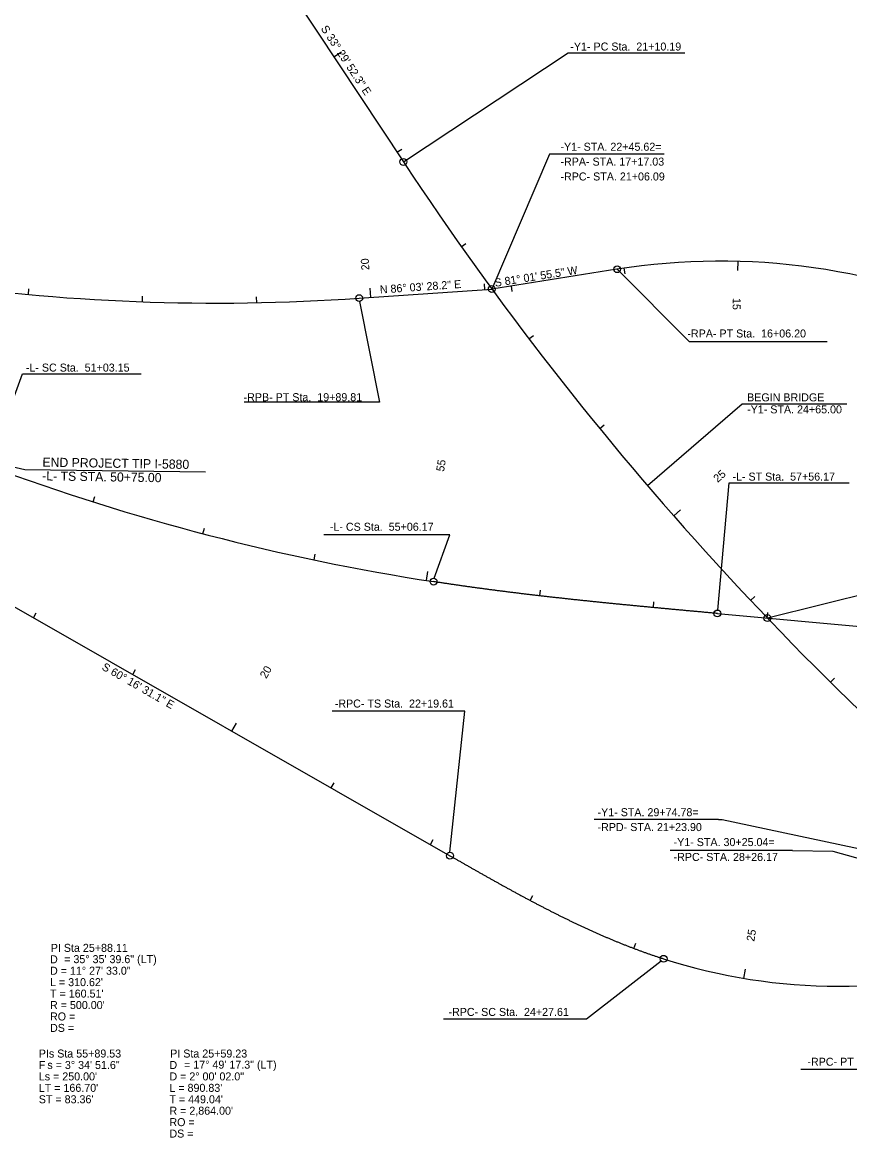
# Model space of a CAD drawing. Extents: x 1636713 to 1642783, y 841520 to 844371.
# Drawn here: x 1640618 to 1641342, y 841942 to 842918 of the extents above; entities that cross this region are included whole.
import ezdxf

# ---------------------------------------------------------------- set-up
doc = ezdxf.new("R2010")
doc.units = 0
for name, color, linetype in [('COGO Default Chain', 7, 'Continuous'), ('Prop DSN White Annotation Label', 7, 'Continuous'), ('Prop Horizontal Alignment', 7, 'Continuous'), ('Prop Horizontal Alignment Curve and Spiral Data', 7, 'Continuous'), ('Prop Horizontal Alignment Direction Label', 7, 'Continuous'), ('Prop Horizontal Alignment Station Label', 7, 'Continuous'), ('Prop Horizontal Alignment Tick Label', 7, 'Continuous'), ('Prop Horizontal Alignment Tick Large', 7, 'Continuous'), ('Prop Horizontal Alignment Tick Small', 7, 'Continuous')]:
    doc.layers.add(name, color=color, linetype=linetype)

msp = doc.modelspace()

# ---------------------------------------------------------------- linework, layer by layer
at = {"layer": 'COGO Default Chain'}
msp.add_line((1640839.83, 842964.49), (1640951.46, 842795.82), dxfattribs=at)
msp.add_arc((1643339.77, 844376.48), 2864, 213.49785, 231.31933, dxfattribs=at)
at = {"layer": 'Prop Horizontal Alignment'}
for p, q in [((1640839.83, 842964.49), (1640951.46, 842795.82)), ((1641138.33, 842701.97), (1641028.85, 842684.69)), ((1640912.85, 842676.7), (1641028.85, 842684.69)), ((1640410.49, 842521.24), (1640992.21, 842189.1)), ((1640410.49, 842521.24), (1640992.21, 842189.1)), ((1641226.26, 842400.92), (1642664.13, 842269.93))]:
    msp.add_line(p, q, dxfattribs=at)
for centre, radius, start, end in [((1643339.77, 844376.48), 2864, 213.49785, 231.31933), ((1640787.73, 844492.39), 1820, 249.39267, 273.94216), ((1641228.74, 842129.06), 580, 64.83812, 98.96792), ((1641283.36, 844405.31), 2000, 249.66813, 261.21372), ((1641332.1, 842574.94), 500, 252.19283, 287.78716), ((1641332.1, 842574.94), 500, 252.19283, 287.78716)]:
    msp.add_arc(centre, radius, start, end, dxfattribs=at)
for points in [[(1641226.26, 842400.92), (1641222.89, 842401.23), (1641219.53, 842401.53), (1641216.16, 842401.84), (1641212.8, 842402.15), (1641209.43, 842402.45), (1641206.07, 842402.76), (1641202.71, 842403.07), (1641199.34, 842403.38), (1641195.98, 842403.69), (1641192.61, 842404), (1641189.25, 842404.31), (1641185.89, 842404.62), (1641182.52, 842404.93), (1641179.16, 842405.25), (1641175.79, 842405.56), (1641172.43, 842405.88), (1641169.07, 842406.19), (1641165.7, 842406.51), (1641162.34, 842406.83), (1641158.98, 842407.15), (1641155.61, 842407.47), (1641152.25, 842407.8), (1641148.89, 842408.13), (1641145.53, 842408.45), (1641142.16, 842408.78), (1641138.8, 842409.11), (1641135.44, 842409.45), (1641132.08, 842409.78), (1641128.72, 842410.12), (1641125.36, 842410.46), (1641121.99, 842410.8), (1641118.63, 842411.15), (1641115.27, 842411.49), (1641111.91, 842411.84), (1641108.55, 842412.2), (1641105.19, 842412.55), (1641101.83, 842412.91), (1641098.48, 842413.27), (1641095.12, 842413.63), (1641091.76, 842414), (1641088.4, 842414.37), (1641085.04, 842414.74), (1641081.68, 842415.12), (1641078.33, 842415.5), (1641074.97, 842415.88), (1641071.61, 842416.26), (1641068.26, 842416.65), (1641064.9, 842417.05), (1641061.55, 842417.44), (1641058.19, 842417.84), (1641054.84, 842418.25), (1641051.49, 842418.66), (1641048.13, 842419.07), (1641044.78, 842419.48), (1641041.43, 842419.9), (1641038.08, 842420.33), (1641034.73, 842420.76), (1641031.38, 842421.19), (1641028.03, 842421.63), (1641024.68, 842422.07), (1641021.33, 842422.52), (1641017.98, 842422.97), (1641014.63, 842423.43), (1641011.28, 842423.89), (1641007.94, 842424.35), (1641004.59, 842424.82), (1641001.25, 842425.3), (1640997.9, 842425.78), (1640994.56, 842426.27), (1640991.22, 842426.76), (1640987.88, 842427.25), (1640984.54, 842427.76), (1640981.2, 842428.26), (1640977.86, 842428.78)], [(1640992.21, 842189.1), (1640994.66, 842187.71), (1640997.1, 842186.32), (1640999.54, 842184.92), (1641001.98, 842183.53), (1641004.42, 842182.14), (1641006.86, 842180.75), (1641009.31, 842179.36), (1641011.75, 842177.97), (1641014.2, 842176.58), (1641016.64, 842175.2), (1641019.09, 842173.81), (1641021.54, 842172.43), (1641023.99, 842171.05), (1641026.44, 842169.68), (1641028.89, 842168.3), (1641031.34, 842166.93), (1641033.8, 842165.56), (1641036.25, 842164.2), (1641038.71, 842162.83), (1641041.17, 842161.48), (1641043.64, 842160.12), (1641046.1, 842158.77), (1641048.57, 842157.42), (1641051.04, 842156.08), (1641053.51, 842154.74), (1641055.99, 842153.41), (1641058.46, 842152.08), (1641060.94, 842150.76), (1641063.43, 842149.44), (1641065.91, 842148.13), (1641068.4, 842146.82), (1641070.89, 842145.52), (1641073.39, 842144.23), (1641075.88, 842142.94), (1641078.39, 842141.66), (1641080.89, 842140.38), (1641083.4, 842139.11), (1641085.91, 842137.85), (1641088.43, 842136.6), (1641090.95, 842135.35), (1641093.47, 842134.11), (1641096, 842132.88), (1641098.53, 842131.66), (1641101.06, 842130.44), (1641103.6, 842129.24), (1641106.14, 842128.04), (1641108.69, 842126.85), (1641111.24, 842125.67), (1641113.8, 842124.5), (1641116.36, 842123.34), (1641118.92, 842122.19), (1641121.49, 842121.05), (1641124.06, 842119.92), (1641126.64, 842118.8), (1641129.22, 842117.69), (1641131.81, 842116.59), (1641134.4, 842115.5), (1641137, 842114.42), (1641139.6, 842113.36), (1641142.2, 842112.3), (1641144.82, 842111.26), (1641147.43, 842110.23), (1641150.05, 842109.21), (1641152.68, 842108.21), (1641155.31, 842107.22), (1641157.94, 842106.24), (1641160.58, 842105.27), (1641163.22, 842104.32), (1641165.87, 842103.38), (1641168.53, 842102.46), (1641171.19, 842101.54), (1641173.85, 842100.65), (1641176.52, 842099.77), (1641179.19, 842098.9)], [(1640992.21, 842189.1), (1640994.66, 842187.71), (1640997.1, 842186.32), (1640999.54, 842184.92), (1641001.98, 842183.53), (1641004.42, 842182.14), (1641006.86, 842180.75), (1641009.31, 842179.36), (1641011.75, 842177.97), (1641014.2, 842176.58), (1641016.64, 842175.2), (1641019.09, 842173.81), (1641021.54, 842172.43), (1641023.99, 842171.05), (1641026.44, 842169.68), (1641028.89, 842168.3), (1641031.34, 842166.93), (1641033.8, 842165.56), (1641036.25, 842164.2), (1641038.71, 842162.83), (1641041.17, 842161.48), (1641043.64, 842160.12), (1641046.1, 842158.77), (1641048.57, 842157.42), (1641051.04, 842156.08), (1641053.51, 842154.74), (1641055.99, 842153.41), (1641058.46, 842152.08), (1641060.94, 842150.76), (1641063.43, 842149.44), (1641065.91, 842148.13), (1641068.4, 842146.82), (1641070.89, 842145.52), (1641073.39, 842144.23), (1641075.88, 842142.94), (1641078.39, 842141.66), (1641080.89, 842140.38), (1641083.4, 842139.11), (1641085.91, 842137.85), (1641088.43, 842136.6), (1641090.95, 842135.35), (1641093.47, 842134.11), (1641096, 842132.88), (1641098.53, 842131.66), (1641101.06, 842130.44), (1641103.6, 842129.24), (1641106.14, 842128.04), (1641108.69, 842126.85), (1641111.24, 842125.67), (1641113.8, 842124.5), (1641116.36, 842123.34), (1641118.92, 842122.19), (1641121.49, 842121.05), (1641124.06, 842119.92), (1641126.64, 842118.8), (1641129.22, 842117.69), (1641131.81, 842116.59), (1641134.4, 842115.5), (1641137, 842114.42), (1641139.6, 842113.36), (1641142.2, 842112.3), (1641144.82, 842111.26), (1641147.43, 842110.23), (1641150.05, 842109.21), (1641152.68, 842108.21), (1641155.31, 842107.22), (1641157.94, 842106.24), (1641160.58, 842105.27), (1641163.22, 842104.32), (1641165.87, 842103.38), (1641168.53, 842102.46), (1641171.19, 842101.54), (1641173.85, 842100.65), (1641176.52, 842099.77), (1641179.19, 842098.9)]]:
    msp.add_spline(points, degree=3, dxfattribs=at)
at = {"layer": 'Prop Horizontal Alignment Station Label'}
for p, q in [((1641179.73, 842802.61), (1641085.92, 842802.61)), ((1641227.32, 842220.63), (1641118.38, 842220.63)), ((1641292.1, 842193.51), (1641184.92, 842193.51))]:
    msp.add_line(p, q, dxfattribs=at)
for points in [[(1640951.46, 842795.82), (1641095.63, 842891.24), (1641197.75, 842891.24)], [(1641179.73, 842802.61), (1641079.4, 842802.61), (1641028.85, 842684.69)], [(1641138.56, 842702), (1641201.69, 842638.92), (1641322.4, 842638.92)], [(1640913.06, 842673.7), (1640930.46, 842585.67), (1640812.03, 842585.67)], [(1640589.49, 842532.73), (1640618.29, 842610.47), (1640722.12, 842610.47)], [(1641165.01, 842512.91), (1641248.01, 842584.13), (1641339.41, 842584.13)], [(1640778.33, 842524.61), (1640620.11, 842526.65), (1640562.11, 842539.88)], [(1641226.53, 842403.91), (1641236.66, 842515.12), (1641341.66, 842515.12)], [(1640978.35, 842431.74), (1640992.02, 842469.58), (1640882.02, 842469.58)], [(1641473.62, 842420.12), (1641364.05, 842420.12), (1641270.02, 842396.93)], [(1640992.21, 842192.1), (1641005.41, 842315.48), (1640889.19, 842315.48)], [(1641227.32, 842220.63), (1641230.55, 842220.63), (1641529.43, 842157.22)], [(1641292.1, 842193.51), (1641327.22, 842192.92), (1641568.58, 842125.71)], [(1641177.07, 842096.78), (1641111.68, 842046.27), (1640986.68, 842046.27)], [(1641483.51, 842096.23), (1641429.23, 842002.14), (1641299.23, 842002.14)]]:
    msp.add_lwpolyline(points, dxfattribs=at)
for centre in [(1640951.46, 842795.82), (1641138.56, 842702), (1641028.85, 842684.69), (1640912.85, 842676.7), (1640977.86, 842428.78), (1641226.26, 842400.92), (1641270.02, 842396.93), (1640992.21, 842189.1), (1641179.19, 842098.9)]:
    msp.add_circle(centre, 3, dxfattribs=at)
at = {"layer": 'Prop Horizontal Alignment Tick Large'}
for p, q in [((1640890.65, 842887.71), (1640897.32, 842892.12)), ((1641244.16, 842708.85), (1641243.95, 842700.86)), ((1640923.01, 842677.4), (1640922.46, 842685.38)), ((1641188.03, 842486.38), (1641194.04, 842491.66)), ((1640971.76, 842429.73), (1640973.01, 842437.63)), ((1640801.5, 842297.99), (1640805.47, 842304.94)), ((1641249.48, 842081.82), (1641250.8, 842089.71))]:
    msp.add_line(p, q, dxfattribs=at)
at = {"layer": 'Prop Horizontal Alignment Tick Small'}
for p, q in [((1640945.84, 842804.32), (1640950.01, 842807.08)), ((1641002.2, 842721.72), (1641006.28, 842724.61)), ((1641144.46, 842702.9), (1641145.19, 842697.95)), ((1641022.78, 842684.27), (1641022.43, 842689.26)), ((1641045.68, 842687.35), (1641046.46, 842682.41)), ((1640623.36, 842679.83), (1640623.81, 842684.81)), ((1640723.15, 842673.54), (1640723.33, 842678.53)), ((1640823.14, 842672.73), (1640823.04, 842677.73)), ((1641061.39, 842641.12), (1641065.37, 842644.15)), ((1641123.36, 842562.64), (1641127.23, 842565.81)), ((1640680.03, 842498.48), (1640681.54, 842503.24)), ((1640776.09, 842470.71), (1640777.36, 842475.54)), ((1640873.41, 842447.77), (1640874.44, 842452.67)), ((1641070.86, 842416.35), (1641071.43, 842421.32)), ((1641255.32, 842412.41), (1641258.96, 842415.84)), ((1641170.32, 842406.07), (1641170.79, 842411.05)), ((1640627.82, 842397.16), (1640630.3, 842401.5)), ((1641269.91, 842396.94), (1641270.36, 842401.92)), ((1640714.66, 842347.57), (1640717.14, 842351.92)), ((1641325.16, 842340.84), (1641328.67, 842344.4)), ((1640888.35, 842248.41), (1640890.82, 842252.75)), ((1640975.19, 842198.82), (1640977.67, 842203.17)), ((1641062.44, 842149.97), (1641064.78, 842154.38)), ((1641153.14, 842108.03), (1641154.92, 842112.71))]:
    msp.add_line(p, q, dxfattribs=at)

# ---------------------------------------------------------------- texts
at = {"layer": 'Prop DSN White Annotation Label'}
for s, p in [('END PROJECT TIP I-5880', (1640635.62, 842529.32)), ('-L- TS STA. 50+75.00', (1640635.43, 842517.33))]:
    msp.add_text(s, height=8, rotation=359.10989, dxfattribs=at).set_placement(p)
at = {"layer": 'Prop Horizontal Alignment Curve and Spiral Data'}
for s, p in [('PI Sta 25+88.11', (1640642.96, 842104.99)), ('D', (1640642.29, 842094.99)), ('= 35%%d 35\' 39.6" (LT)', (1640654.7, 842095.11)), ('D = 11%%d 27\' 33.0"', (1640642.29, 842084.99)), ("L = 310.62'", (1640642.29, 842074.99)), ("T = 160.51'", (1640642.29, 842064.99)), ("R = 500.00'", (1640642.29, 842054.99)), ('RO = ', (1640642.29, 842044.99)), ('DS =', (1640642.29, 842034.99)), ('PIs Sta 55+89.53', (1640632.46, 842012.57)), ('PI Sta 25+59.23', (1640747.44, 842012.57)), ('F', (1640632.46, 842002.57)), ('s = 3%%d 34\' 51.6"', (1640639.97, 842002.57)), ('D', (1640746.76, 842002.57)), ('= 17%%d 49\' 17.3" (LT)', (1640759.61, 842002.86)), ("Ls = 250.00'", (1640632.46, 841992.57)), ('D = 2%%d 00\' 02.0"', (1640746.76, 841992.57)), ("LT = 166.70'", (1640632.46, 841982.57)), ("L = 890.83'", (1640746.76, 841982.57)), ("ST = 83.36'", (1640632.46, 841972.57)), ("T = 449.04'", (1640746.76, 841972.57)), ("R = 2,864.00'", (1640746.76, 841962.57)), ('RO = ', (1640746.76, 841952.57)), ('DS =', (1640746.76, 841942.57))]:
    msp.add_text(s, height=7, dxfattribs=at).set_placement(p)
at = {"layer": 'Prop Horizontal Alignment Direction Label'}
for s, rotation, p in [('S 33%%d 29\' 52.3" E', 303.49785, (1640878.98, 842912.38)), ('S 81%%d 01\' 55.5" W', 8.96792, (1641031.89, 842686.59)), ('N 86%%d 03\' 28.2" E', 3.94216, (1640931.14, 842680.7)), ('S 60%%d 16\' 31.1" E', 330.27531, (1640687.01, 842352.23))]:
    msp.add_text(s, height=7, rotation=rotation, dxfattribs=at).set_placement(p)
at = {"layer": 'Prop Horizontal Alignment Station Label'}
for s, p in [('-Y1- PC Sta.  21+10.19', (1641097.56, 842893.24)), ('-L- SC Sta.  51+03.15', (1640621.12, 842612.47)), ('-RPB- PT Sta.  19+89.81', (1640811.63, 842586.59)), ('BEGIN BRIDGE', (1641252.26, 842586.43)), ('-Y1- STA. 24+65.00', (1641252.26, 842575.93)), ('-RPC- TS Sta.  22+19.61', (1640891.44, 842318.66)), ('-RPC- SC Sta.  24+27.61', (1640990.94, 842048.95)), ('-RPC- PT Sta.  27+38.23', (1641305.02, 842005.39))]:
    msp.add_text(s, height=7, rotation=360, dxfattribs=at).set_placement(p)
for s, p in [('-Y1- STA. 22+45.62=', (1641088.92, 842805.61)), ('-RPA- STA. 17+17.03', (1641088.92, 842792.61)), ('-RPC- STA. 21+06.09', (1641088.92, 842779.61)), ('-RPA- PT Sta.  16+06.20', (1641200, 842642.3)), ('-L- ST Sta.  57+56.17', (1641239.43, 842517.12)), ('-L- CS Sta.  55+06.17', (1640887.15, 842473.27)), ('-Y1- STA. 29+74.78=', (1641121.38, 842223.63)), ('-RPD- STA. 21+23.90', (1641121.38, 842210.63)), ('-Y1- STA. 30+25.04=', (1641187.92, 842197.49)), ('-RPC- STA. 28+26.17', (1641187.92, 842184.49))]:
    msp.add_text(s, height=7, dxfattribs=at).set_placement(p)
at = {"layer": 'Prop Horizontal Alignment Tick Label'}
for s, rotation, p in [('20', 93.94216, (1640921.79, 842701.32)), ('15', 268.4767, (1641239.81, 842676.9)), ('55', 81.03696, (1640987.02, 842524.68)), ('25', 41.29628, (1641226.51, 842515.07)), ('20', 60.27531, (1640831.51, 842343.47)), ('25', 80.4885, (1641258.52, 842113.72))]:
    msp.add_text(s, height=7, rotation=rotation, dxfattribs=at).set_placement(p)

doc.saveas('drawing.dxf')
